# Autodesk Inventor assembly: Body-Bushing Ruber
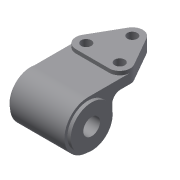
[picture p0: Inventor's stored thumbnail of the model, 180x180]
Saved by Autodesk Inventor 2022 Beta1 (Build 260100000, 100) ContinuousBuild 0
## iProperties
Created: 2011-07
Part Number: Body-Bushing Ruber
Document SubType Name: Assembly
Designer: CadCim
Author: CadCim
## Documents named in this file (3)
- D:\PROJECTS_2021\Resources\Tutorial Files\c09_Inv_2022_tut\c09_Inv_2021_tut\c09_Inv_tut_2021\c09_tut03_inv\Anti Vibration Mount\Body-Bushing Ruber.iam
- D:\PROJECTS_2021\Resources\Tutorial Files\c09_Inv_2022_tut\c09_Inv_2021_tut\c09_Inv_tut_2021\c09_tut03_inv\Anti Vibration Mount\Body.ipt
- D:\PROJECTS_2021\Resources\Tutorial Files\c09_Inv_2022_tut\c09_Inv_2021_tut\c09_Inv_tut_2021\c09_tut03_inv\Anti Vibration Mount\Bushing Rubber.ipt
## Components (3 placed, 2 different names)
1. Body:1 — Insert:1, Insert:2
2. Bushing Rubber:1 — Insert:1
3. Bushing Rubber:2 — Insert:2
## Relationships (2: Insert 2)
- Insert:1: Body:1 ↔ Bushing Rubber:1
- Insert:2: Body:1 ↔ Bushing Rubber:2
